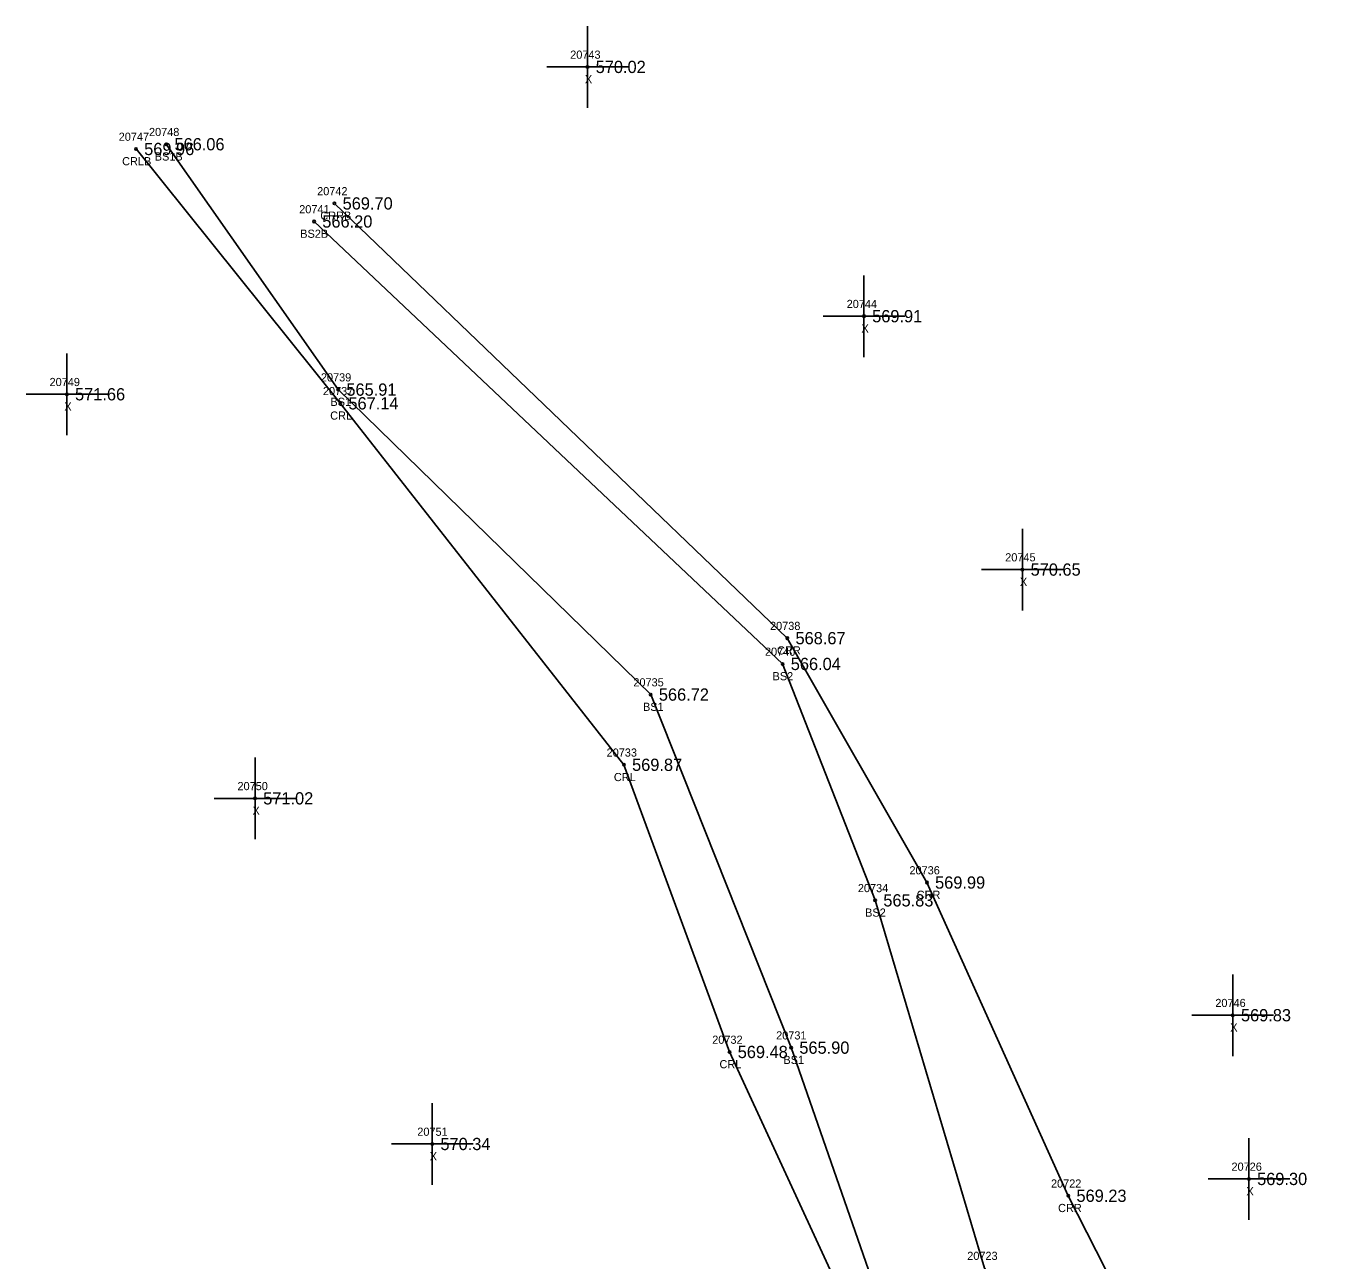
# Model space of a CAD drawing. Extents: x 1530159 to 1531652, y 877045 to 877724.
# Drawn here: x 1530595.8 to 1530755.4, y 877573 to 877724.2 of the extents above; entities that cross this region are included whole.
import ezdxf

# ---------------------------------------------------------------- set-up
doc = ezdxf.new("R2010")
doc.units = 0
for name, color, linetype in [('RD_DTM_BkLn2', 7, 'Continuous'), ('RD_DTM_BkLn_txCode', 7, 'Continuous'), ('RD_EX_H2O', 7, 'Continuous'), ('RD_EX_H2O_txCode', 7, 'Continuous'), ('RD_EX_Misc', 7, 'Continuous'), ('RD_EX_Misc_txCode', 7, 'Continuous'), ('RD_EX_TX_H2O_ELEV', 7, 'Continuous'), ('RD_EX_TX_Misc_ELEV', 7, 'Continuous'), ('RD_SMD_Locator', 7, 'Continuous')]:
    doc.layers.add(name, color=color, linetype=linetype)

msp = doc.modelspace()

# ---------------------------------------------------------------- linework, layer by layer
at = {"layer": 'RD_DTM_BkLn2'}
for points in [[(1530978.51, 877193.14), (1530957.83, 877217.34), (1530939.69, 877236.27), (1530919.92, 877243.6), (1530901.7, 877240.19), (1530890.91, 877253.72), (1530883.61, 877289.66), (1530871.34, 877309.06), (1530854.23, 877336.62), (1530832.44, 877361.15), (1530819.05, 877374.38), (1530808.85, 877385.69), (1530794.67, 877405.25), (1530798.76, 877416.08), (1530761.4, 877471.05), (1530729.88, 877527.47), (1530702.64, 877561.57), (1530689.57, 877599.12), (1530672.36, 877642.36), (1530634.08, 877679.71), (1530613.02, 877709.76)], [(1530924.53, 877258.32), (1530897.88, 877293.87), (1530872.66, 877332.29), (1530858.92, 877351.67), (1530825.26, 877389.74), (1530809.31, 877429.86), (1530783.89, 877460.41), (1530770.73, 877490.54), (1530744.62, 877534.44), (1530713.25, 877572.12), (1530699.86, 877617.16), (1530688.52, 877646.11), (1530631.13, 877700.3)]]:
    msp.add_lwpolyline(points, dxfattribs=at)
at = {"layer": 'RD_EX_H2O'}
for points in [[(1530806.6, 877384.6), (1530793.1, 877403.61), (1530793.09, 877415.71), (1530759.45, 877470.01), (1530725.85, 877522.95), (1530701.01, 877557.5), (1530682.02, 877598.59), (1530669.08, 877633.76), (1530634.33, 877678.03), (1530609.31, 877709.18)], [(1530922.5, 877289.86), (1530895.04, 877301.24), (1530872.88, 877333.85), (1530860.22, 877363.17), (1530828.43, 877393.28), (1530808.3, 877433.62), (1530784.24, 877462.07), (1530773.36, 877492.12), (1530746.47, 877535.88), (1530723.52, 877580.98), (1530706.2, 877619.34), (1530689.1, 877649.27), (1530633.62, 877702.51)]]:
    msp.add_lwpolyline(points, dxfattribs=at)
at = {"layer": 'RD_EX_Misc'}
for p, q in [((1530664.62, 877714.23), (1530664.62, 877724.23)), ((1530659.62, 877719.23), (1530669.62, 877719.23)), ((1530698.49, 877683.7), (1530698.49, 877693.7)), ((1530693.49, 877688.7), (1530703.49, 877688.7)), ((1530600.84, 877674.14), (1530600.84, 877684.14)), ((1530595.84, 877679.14), (1530605.84, 877679.14)), ((1530717.9, 877652.67), (1530717.9, 877662.67)), ((1530712.9, 877657.67), (1530722.9, 877657.67)), ((1530623.89, 877624.65), (1530623.89, 877634.65)), ((1530618.89, 877629.65), (1530628.89, 877629.65)), ((1530743.67, 877598.09), (1530743.67, 877608.09)), ((1530738.67, 877603.09), (1530748.67, 877603.09)), ((1530645.6, 877582.32), (1530645.6, 877592.32)), ((1530640.6, 877587.32), (1530650.6, 877587.32)), ((1530745.65, 877578.04), (1530745.65, 877588.04)), ((1530740.65, 877583.04), (1530750.65, 877583.04))]:
    msp.add_line(p, q, dxfattribs=at)
at = {"layer": 'RD_SMD_Locator'}
for centre in [(1530664.62, 877719.23), (1530609.31, 877709.18), (1530613.02, 877709.76), (1530633.62, 877702.51), (1530631.13, 877700.3), (1530698.49, 877688.7), (1530634.08, 877679.71), (1530600.84, 877679.14), (1530634.33, 877678.03), (1530717.9, 877657.67), (1530689.1, 877649.27), (1530688.52, 877646.11), (1530672.36, 877642.36), (1530669.08, 877633.76), (1530623.89, 877629.65), (1530706.2, 877619.34), (1530699.86, 877617.16), (1530743.67, 877603.09), (1530682.02, 877598.59), (1530689.57, 877599.12), (1530645.6, 877587.32), (1530745.65, 877583.04), (1530723.52, 877580.98)]:
    msp.add_circle(centre, 0.15, dxfattribs=at)

# ---------------------------------------------------------------- texts
at = {"layer": 'RD_DTM_BkLn_txCode'}
for s, p in [('20748', (1530610.9, 877710.76)), ('BS1B', (1530611.61, 877707.76)), ('20741', (1530629.3, 877701.3)), ('BS2B', (1530629.43, 877698.3)), ('20739', (1530631.96, 877680.71)), ('BS1', (1530633.13, 877677.71)), ('20740', (1530686.36, 877647.11)), ('BS2', (1530687.29, 877644.11)), ('20735', (1530670.24, 877643.36)), ('BS1', (1530671.42, 877640.36)), ('20734', (1530697.74, 877618.16)), ('BS2', (1530698.63, 877615.16)), ('20731', (1530687.73, 877600.12)), ('BS1', (1530688.62, 877597.12)), ('20723', (1530711.14, 877573.12))]:
    msp.add_text(s, height=1, dxfattribs=at).set_placement(p)
at = {"layer": 'RD_EX_H2O_txCode'}
for s, p in [('20747', (1530607.19, 877710.18)), ('CRLB', (1530607.61, 877707.18)), ('20742', (1530631.5, 877703.51)), ('CRRB', (1530631.89, 877700.51)), ('20737', (1530632.21, 877679.03)), ('CRL', (1530633.1, 877676.03)), ('20738', (1530686.98, 877650.27)), ('CRR', (1530687.85, 877647.27)), ('20733', (1530666.96, 877634.76)), ('CRL', (1530667.85, 877631.76)), ('20736', (1530704.06, 877620.34)), ('CRR', (1530704.95, 877617.34)), ('20732', (1530679.9, 877599.59)), ('CRL', (1530680.79, 877596.59)), ('20722', (1530721.4, 877581.98)), ('CRR', (1530722.27, 877578.98))]:
    msp.add_text(s, height=1, dxfattribs=at).set_placement(p)
at = {"layer": 'RD_EX_Misc_txCode'}
for s, p in [('20743', (1530662.5, 877720.23)), ('X', (1530664.3, 877717.23)), ('20744', (1530696.37, 877689.7)), ('X', (1530698.18, 877686.7)), ('20749', (1530598.72, 877680.14)), ('X', (1530600.53, 877677.14)), ('20745', (1530715.79, 877658.67)), ('X', (1530717.59, 877655.67)), ('20750', (1530621.74, 877630.65)), ('X', (1530623.58, 877627.65)), ('20746', (1530741.53, 877604.09)), ('X', (1530743.36, 877601.09)), ('20751', (1530643.77, 877588.32)), ('X', (1530645.29, 877585.32)), ('20726', (1530743.51, 877584.04)), ('X', (1530745.34, 877581.04))]:
    msp.add_text(s, height=1, dxfattribs=at).set_placement(p)
at = {"layer": 'RD_EX_TX_H2O_ELEV'}
for s, p in [('569.96', (1530610.31, 877708.43)), ('569.70', (1530634.62, 877701.76)), ('567.14', (1530635.33, 877677.28)), ('568.67', (1530690.1, 877648.52)), ('569.87', (1530670.08, 877633.01)), ('569.99', (1530707.2, 877618.59)), ('569.48', (1530683.02, 877597.84)), ('569.23', (1530724.52, 877580.23))]:
    msp.add_text(s, height=1.5, dxfattribs=at).set_placement(p)
at = {"layer": 'RD_EX_TX_Misc_ELEV'}
for s, p in [('570.02', (1530665.62, 877718.48)), ('566.06', (1530614.02, 877709.01)), ('566.20', (1530632.13, 877699.55)), ('569.91', (1530699.49, 877687.95)), ('571.66', (1530601.84, 877678.39)), ('565.91', (1530635.08, 877678.96)), ('570.65', (1530718.9, 877656.92)), ('566.04', (1530689.52, 877645.36)), ('566.72', (1530673.36, 877641.61)), ('571.02', (1530624.89, 877628.9)), ('565.83', (1530700.86, 877616.41)), ('569.83', (1530744.67, 877602.34)), ('565.90', (1530690.57, 877598.37)), ('570.34', (1530646.6, 877586.57)), ('569.30', (1530746.65, 877582.29))]:
    msp.add_text(s, height=1.5, dxfattribs=at).set_placement(p)

doc.saveas('drawing.dxf')
